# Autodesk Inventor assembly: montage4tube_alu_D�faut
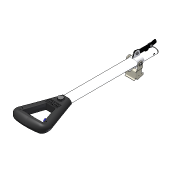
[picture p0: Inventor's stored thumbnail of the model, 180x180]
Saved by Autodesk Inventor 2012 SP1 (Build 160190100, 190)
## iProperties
Created: 2011-01
Part Number: montage4tube_alu_D�faut
Document SubType Name: Assembly
Designer: eric
Mass: 291.278 g
Surface Area: 2742.8 cm^2
Volume: 291.278 cm^3
Density: 1 g/cm^3
Author: eric
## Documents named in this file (18)
- D:\Cours\Inventor salle SI\chariot_de_golf_2008\chariot_de_golf_trolem\montage4tube_alu_Defaut.iam
- D:\Cours\Inventor salle SI\chariot_de_golf_2008\chariot_de_golf_trolem\46vis_a_metaux_M6_10.ipt
- D:\Cours\Inventor salle SI\chariot_de_golf_2008\chariot_de_golf_trolem\36Ecrou H_ FR_ M6.ipt
- D:\Cours\Inventor salle SI\chariot_de_golf_2008\chariot_de_golf_trolem\24poignee_femelle_Defaut.ipt
- D:\Cours\Inventor salle SI\chariot_de_golf_2008\chariot_de_golf_trolem\27chape_verrou_haut_Defaut.ipt
- D:\Cours\Inventor salle SI\chariot_de_golf_2008\chariot_de_golf_trolem\56VisChc_M8_35_Defaut.ipt
- D:\Cours\Inventor salle SI\chariot_de_golf_2008\chariot_de_golf_trolem\63chape_de_cable_Defaut.ipt
- D:\Cours\Inventor salle SI\chariot_de_golf_2008\chariot_de_golf_trolem\25_verrou_haut_Defaut.ipt
- D:\Cours\Inventor salle SI\chariot_de_golf_2008\chariot_de_golf_trolem\4tube_alu_Defaut.ipt
- D:\Cours\Inventor salle SI\chariot_de_golf_2008\chariot_de_golf_trolem\55cache_vis_Defaut.ipt
- D:\Cours\Inventor salle SI\chariot_de_golf_2008\chariot_de_golf_trolem\67Vis _a_ metaux_M3x25.ipt
- D:\Cours\Inventor salle SI\chariot_de_golf_2008\chariot_de_golf_trolem\52biellette_Defaut.ipt
- D:\Cours\Inventor salle SI\chariot_de_golf_2008\chariot_de_golf_trolem\24poignee_male_Defaut.ipt
- D:\Cours\Inventor salle SI\chariot_de_golf_2008\chariot_de_golf_trolem\75commande_Defaut.ipt
- D:\Cours\Inventor salle SI\chariot_de_golf_2008\chariot_de_golf_trolem\35Vis_CBLZ_M6_55.ipt
- D:\Cours\Inventor salle SI\chariot_de_golf_2008\chariot_de_golf_trolem\58embout_ovale_Defaut.ipt
- D:\Cours\Inventor salle SI\chariot_de_golf_2008\chariot_de_golf_trolem\26ressort_verrou_haut_Defaut.ipt
- D:\Cours\Inventor salle SI\chariot_de_golf_2008\chariot_de_golf_trolem\66rivet_Defaut.ipt
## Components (23 placed, 17 different names)
1. 46vis_a_metaux_M6_10:1
2. 36Ecrou H_ FR_ M6:1
3. 24poignee_femelle_Defaut:1
4. 27chape_verrou_haut_Defaut:1
5. 56VisChc_M8_35_Defaut:1
6. 63chape_de_cable_Defaut:1
7. 25_verrou_haut_Defaut:1
8. 4tube_alu_Defaut:1
9. 55cache_vis_Defaut:1
10. 67Vis _a_ metaux_M3x25:1
11. 52biellette_Defaut:1
12. 55cache_vis_Defaut:2
13. 67Vis _a_ metaux_M3x25:2
14. 36Ecrou H_ FR_ M6:2
15. 36Ecrou H_ FR_ M6:3
16. 46vis_a_metaux_M6_10:2
17. 24poignee_male_Defaut:1
18. 75commande_Defaut:1
19. 36Ecrou H_ FR_ M6:4
20. 35Vis_CBLZ_M6_55:1
21. 58embout_ovale_Defaut:1
22. 26ressort_verrou_haut_Defaut:1
23. 66rivet_Defaut:1
